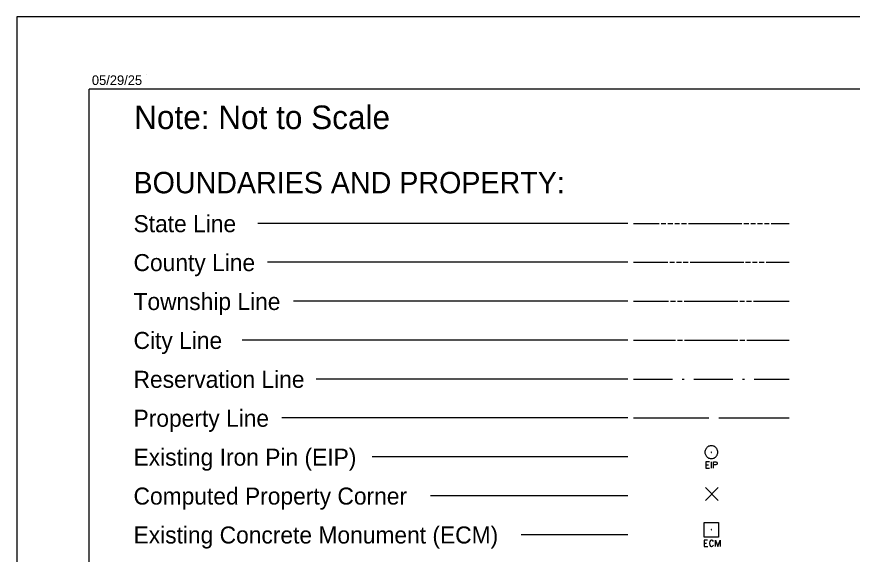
# Model space of a CAD drawing. Extents: x 0 to 3, y 0 to 1.83.
# Drawn here: x 0 to 0.722, y 1.369 to 1.833 of the extents above; entities that cross this region are included whole.
import ezdxf

# ---------------------------------------------------------------- set-up
doc = ezdxf.new("R2010")
doc.units = 0
for name, color, linetype in [('Sheet_Plan', 7, 'Continuous'), ('Sheet_Symbology', 7, 'Continuous'), ('z - Construction', 7, 'Continuous')]:
    doc.layers.add(name, color=color, linetype=linetype)

msp = doc.modelspace()

# ---------------------------------------------------------------- linework, layer by layer
at = {"layer": 'Sheet_Plan'}
for p, q in [((0.11243, 1.78338), (0.11243, 1.78338)), ((0.0625, 0.0625), (0.06249, 1.77083)), ((2.77083, 1.77083), (0.06249, 1.77083))]:
    msp.add_line(p, q, dxfattribs=at)
at = {"layer": 'Sheet_Symbology'}
for p, q in [((0.5278, 1.65472), (0.20832, 1.65472)), ((0.53263, 1.65472), (0.55483, 1.65472)), ((0.55651, 1.65472), (0.56071, 1.65472)), ((0.56239, 1.65472), (0.5666, 1.65472)), ((0.56828, 1.65472), (0.57248, 1.65472)), ((0.57417, 1.65472), (0.57837, 1.65472)), ((0.58005, 1.65472), (0.62629, 1.65472)), ((0.62798, 1.65472), (0.63218, 1.65472)), ((0.63386, 1.65472), (0.63807, 1.65472)), ((0.63975, 1.65472), (0.64395, 1.65472)), ((0.64563, 1.65472), (0.64984, 1.65472)), ((0.65152, 1.65472), (0.66716, 1.65472)), ((0.5278, 1.62109), (0.21671, 1.62109)), ((0.53263, 1.62109), (0.56221, 1.62109)), ((0.56389, 1.62109), (0.56809, 1.62109)), ((0.56977, 1.62109), (0.57398, 1.62109)), ((0.57566, 1.62109), (0.57986, 1.62109)), ((0.58154, 1.62109), (0.62779, 1.62109)), ((0.62947, 1.62109), (0.63367, 1.62109)), ((0.63535, 1.62109), (0.63956, 1.62109)), ((0.64124, 1.62109), (0.64544, 1.62109)), ((0.64712, 1.62109), (0.66716, 1.62109)), ((0.5278, 1.58746), (0.23907, 1.58746)), ((0.53263, 1.58746), (0.56298, 1.58746)), ((0.56467, 1.58746), (0.56887, 1.58746)), ((0.57055, 1.58746), (0.57475, 1.58746)), ((0.57644, 1.58746), (0.62268, 1.58746)), ((0.62436, 1.58746), (0.62856, 1.58746)), ((0.63025, 1.58746), (0.63445, 1.58746)), ((0.63613, 1.58746), (0.66716, 1.58746)), ((0.5278, 1.55382), (0.19473, 1.55382)), ((0.53263, 1.55382), (0.56902, 1.55382)), ((0.5707, 1.55382), (0.5749, 1.55382)), ((0.57658, 1.55382), (0.62283, 1.55382)), ((0.62451, 1.55382), (0.62871, 1.55382)), ((0.63039, 1.55382), (0.66716, 1.55382)), ((0.5278, 1.52019), (0.25862, 1.52019)), ((0.53263, 1.52019), (0.56626, 1.52019)), ((0.57467, 1.52019), (0.57635, 1.52019)), ((0.58476, 1.52019), (0.61839, 1.52019)), ((0.6268, 1.52019), (0.62848, 1.52019)), ((0.63689, 1.52019), (0.66716, 1.52019)), ((0.5278, 1.48656), (0.22904, 1.48656)), ((0.53263, 1.48656), (0.59779, 1.48656)), ((0.6062, 1.48656), (0.66716, 1.48656)), ((0.5278, 1.45293), (0.30703, 1.45293)), ((0.59508, 1.44597), (0.59728, 1.44597)), ((0.59991, 1.44326), (0.59991, 1.44864)), ((0.6058, 1.41523), (0.59469, 1.42634)), ((0.59469, 1.41523), (0.6058, 1.42634)), ((0.5278, 1.4193), (0.35721, 1.4193)), ((0.5278, 1.38567), (0.4356, 1.38567)), ((0.59355, 1.37827), (0.59575, 1.37827))]:
    msp.add_line(p, q, dxfattribs=at)
for points in [[(0.60543, 1.45697), (0.60539, 1.45768), (0.60526, 1.45835), (0.60503, 1.45902), (0.60476, 1.45965), (0.60436, 1.46023), (0.60391, 1.46076), (0.60342, 1.46126), (0.60284, 1.46166), (0.60226, 1.46202), (0.60159, 1.46224), (0.60092, 1.46242), (0.60025, 1.46251), (0.59954, 1.46251), (0.59882, 1.46242), (0.59815, 1.46224), (0.59752, 1.46202), (0.5969, 1.46166), (0.59632, 1.46126), (0.59583, 1.46076), (0.59538, 1.46023), (0.59502, 1.45965), (0.59471, 1.45902), (0.59449, 1.45835), (0.59435, 1.45768), (0.59431, 1.45697), (0.59435, 1.45625), (0.59449, 1.45558), (0.59471, 1.45491), (0.59502, 1.45428), (0.59538, 1.4537), (0.59583, 1.45317), (0.59632, 1.45267), (0.5969, 1.45227), (0.59752, 1.45192), (0.59815, 1.45169), (0.59882, 1.45151), (0.59954, 1.45143), (0.60025, 1.45143), (0.60092, 1.45151), (0.60159, 1.45169), (0.60226, 1.45192), (0.60284, 1.45227), (0.60342, 1.45267), (0.60391, 1.45317), (0.60436, 1.4537), (0.60476, 1.45428), (0.60503, 1.45491), (0.60526, 1.45558), (0.60539, 1.45625), (0.60543, 1.45697)], [(0.59998, 1.4571), (0.59985, 1.45714), (0.59976, 1.45706), (0.59972, 1.45692), (0.5998, 1.45683), (0.59994, 1.45679), (0.60003, 1.45688), (0.60007, 1.45701), (0.59998, 1.4571)], [(0.59817, 1.44864), (0.59508, 1.44864), (0.59508, 1.44326), (0.59839, 1.44326)], [(0.60169, 1.44326), (0.60169, 1.44864), (0.60385, 1.44864), (0.60449, 1.44843), (0.60504, 1.44758), (0.60504, 1.44707), (0.60453, 1.44623), (0.60385, 1.44602), (0.60169, 1.44602)], [(0.59358, 1.39624), (0.60618, 1.39624), (0.60618, 1.38365), (0.59358, 1.38365), (0.59358, 1.39624)], [(0.59985, 1.3901), (0.59979, 1.39004), (0.59979, 1.38992), (0.59991, 1.38979), (0.60004, 1.38985), (0.6001, 1.38998), (0.59998, 1.3901), (0.59985, 1.3901)], [(0.59664, 1.38094), (0.59355, 1.38094), (0.59355, 1.37556), (0.59685, 1.37556)], [(0.60172, 1.37988), (0.60105, 1.38077), (0.60037, 1.38094), (0.5999, 1.38094), (0.59927, 1.38077), (0.59855, 1.37988), (0.59838, 1.37869), (0.59838, 1.37806), (0.59838, 1.37763), (0.59842, 1.37725), (0.59855, 1.37657), (0.59927, 1.37573), (0.5999, 1.37556), (0.60028, 1.37556), (0.601, 1.37573), (0.60172, 1.37657)], [(0.60346, 1.37556), (0.60346, 1.38094), (0.60549, 1.37556), (0.60744, 1.38094), (0.60744, 1.37556)]]:
    msp.add_lwpolyline(points, dxfattribs=at)
at = {"layer": 'z - Construction'}
for p, q in [((2.83333, 1.83333), (0, 1.83333)), ((0, 1.83333), (0, 0))]:
    msp.add_line(p, q, dxfattribs=at)

# ---------------------------------------------------------------- texts
at = {"layer": 'Sheet_Plan'}
msp.add_text('05/29/25', height=0.008333, rotation=0, dxfattribs=at).set_placement((0.06492, 1.77428))
at = {"layer": 'Sheet_Symbology'}
for s, height, p in [('Note: Not to Scale', 0.0203596, (0.10144, 1.73621)), ('BOUNDARIES AND PROPERTY:', 0.0184972, (0.10087, 1.6807)), ('State Line', 0.014714, (0.10089, 1.64709)), ('County Line', 0.0147137, (0.10089, 1.61346)), ('Township Line', 0.0147137, (0.10089, 1.57983)), ('City Line', 0.014714, (0.10089, 1.54619)), ('Reservation Line', 0.0147137, (0.10089, 1.51256)), ('Property Line', 0.0147137, (0.10089, 1.47893)), ('Existing Iron Pin (EIP)', 0.0147137, (0.10089, 1.4453)), ('Computed Property Corner', 0.0147137, (0.10089, 1.41167)), ('Existing Concrete Monument (ECM)', 0.0147137, (0.10089, 1.37804))]:
    msp.add_text(s, height=height, dxfattribs=at).set_placement(p)

doc.saveas('drawing.dxf')
